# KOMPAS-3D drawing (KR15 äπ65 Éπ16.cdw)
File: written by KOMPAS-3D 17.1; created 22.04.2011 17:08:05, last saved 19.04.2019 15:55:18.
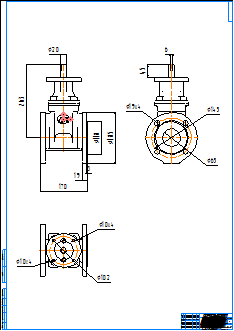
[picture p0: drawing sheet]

Title block, sheet 1: name: KR15 Ду65 Ру16; material: Внимание! Данный продукт является объектом авторского права ООО «Торговый Дом АДЛ». / Запрещается изменение, копирование, распространение / (в том числе путем копирования на другие сайты и ресурсы в Интернете) / или любое иное использование информации и объектов без предварительного / согласия правообладателя (ООО «Торговый Дом АДЛ»).; scale: 1:1; sheets: 1; organisation: ООО "Торговый дом АДЛ"; sheet format: A0; stored path: \\adlc.lan\data\АДЛ_ПКД\3D-модели\ADL production\Клиновые задвижки серии KR ГРАНАР\Клиновые задвижки KR15\С голым штоком\KOMPAS 2D\KR15 Ду65 Ру16.cdw

Views: Спереди 4, Проекционный вид 5, Проекционный вид 6
Dimensions and other numbers on the sheet: 170; 19; 3; 185; 118; 263; 20; 102; 10; 145; 65; 45; 6; 1:1; 1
